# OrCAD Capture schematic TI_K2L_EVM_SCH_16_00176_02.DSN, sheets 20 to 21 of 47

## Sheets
20 PAGE20 : K2L_SOC-DDR3-2: size C; title: DDR3(3)
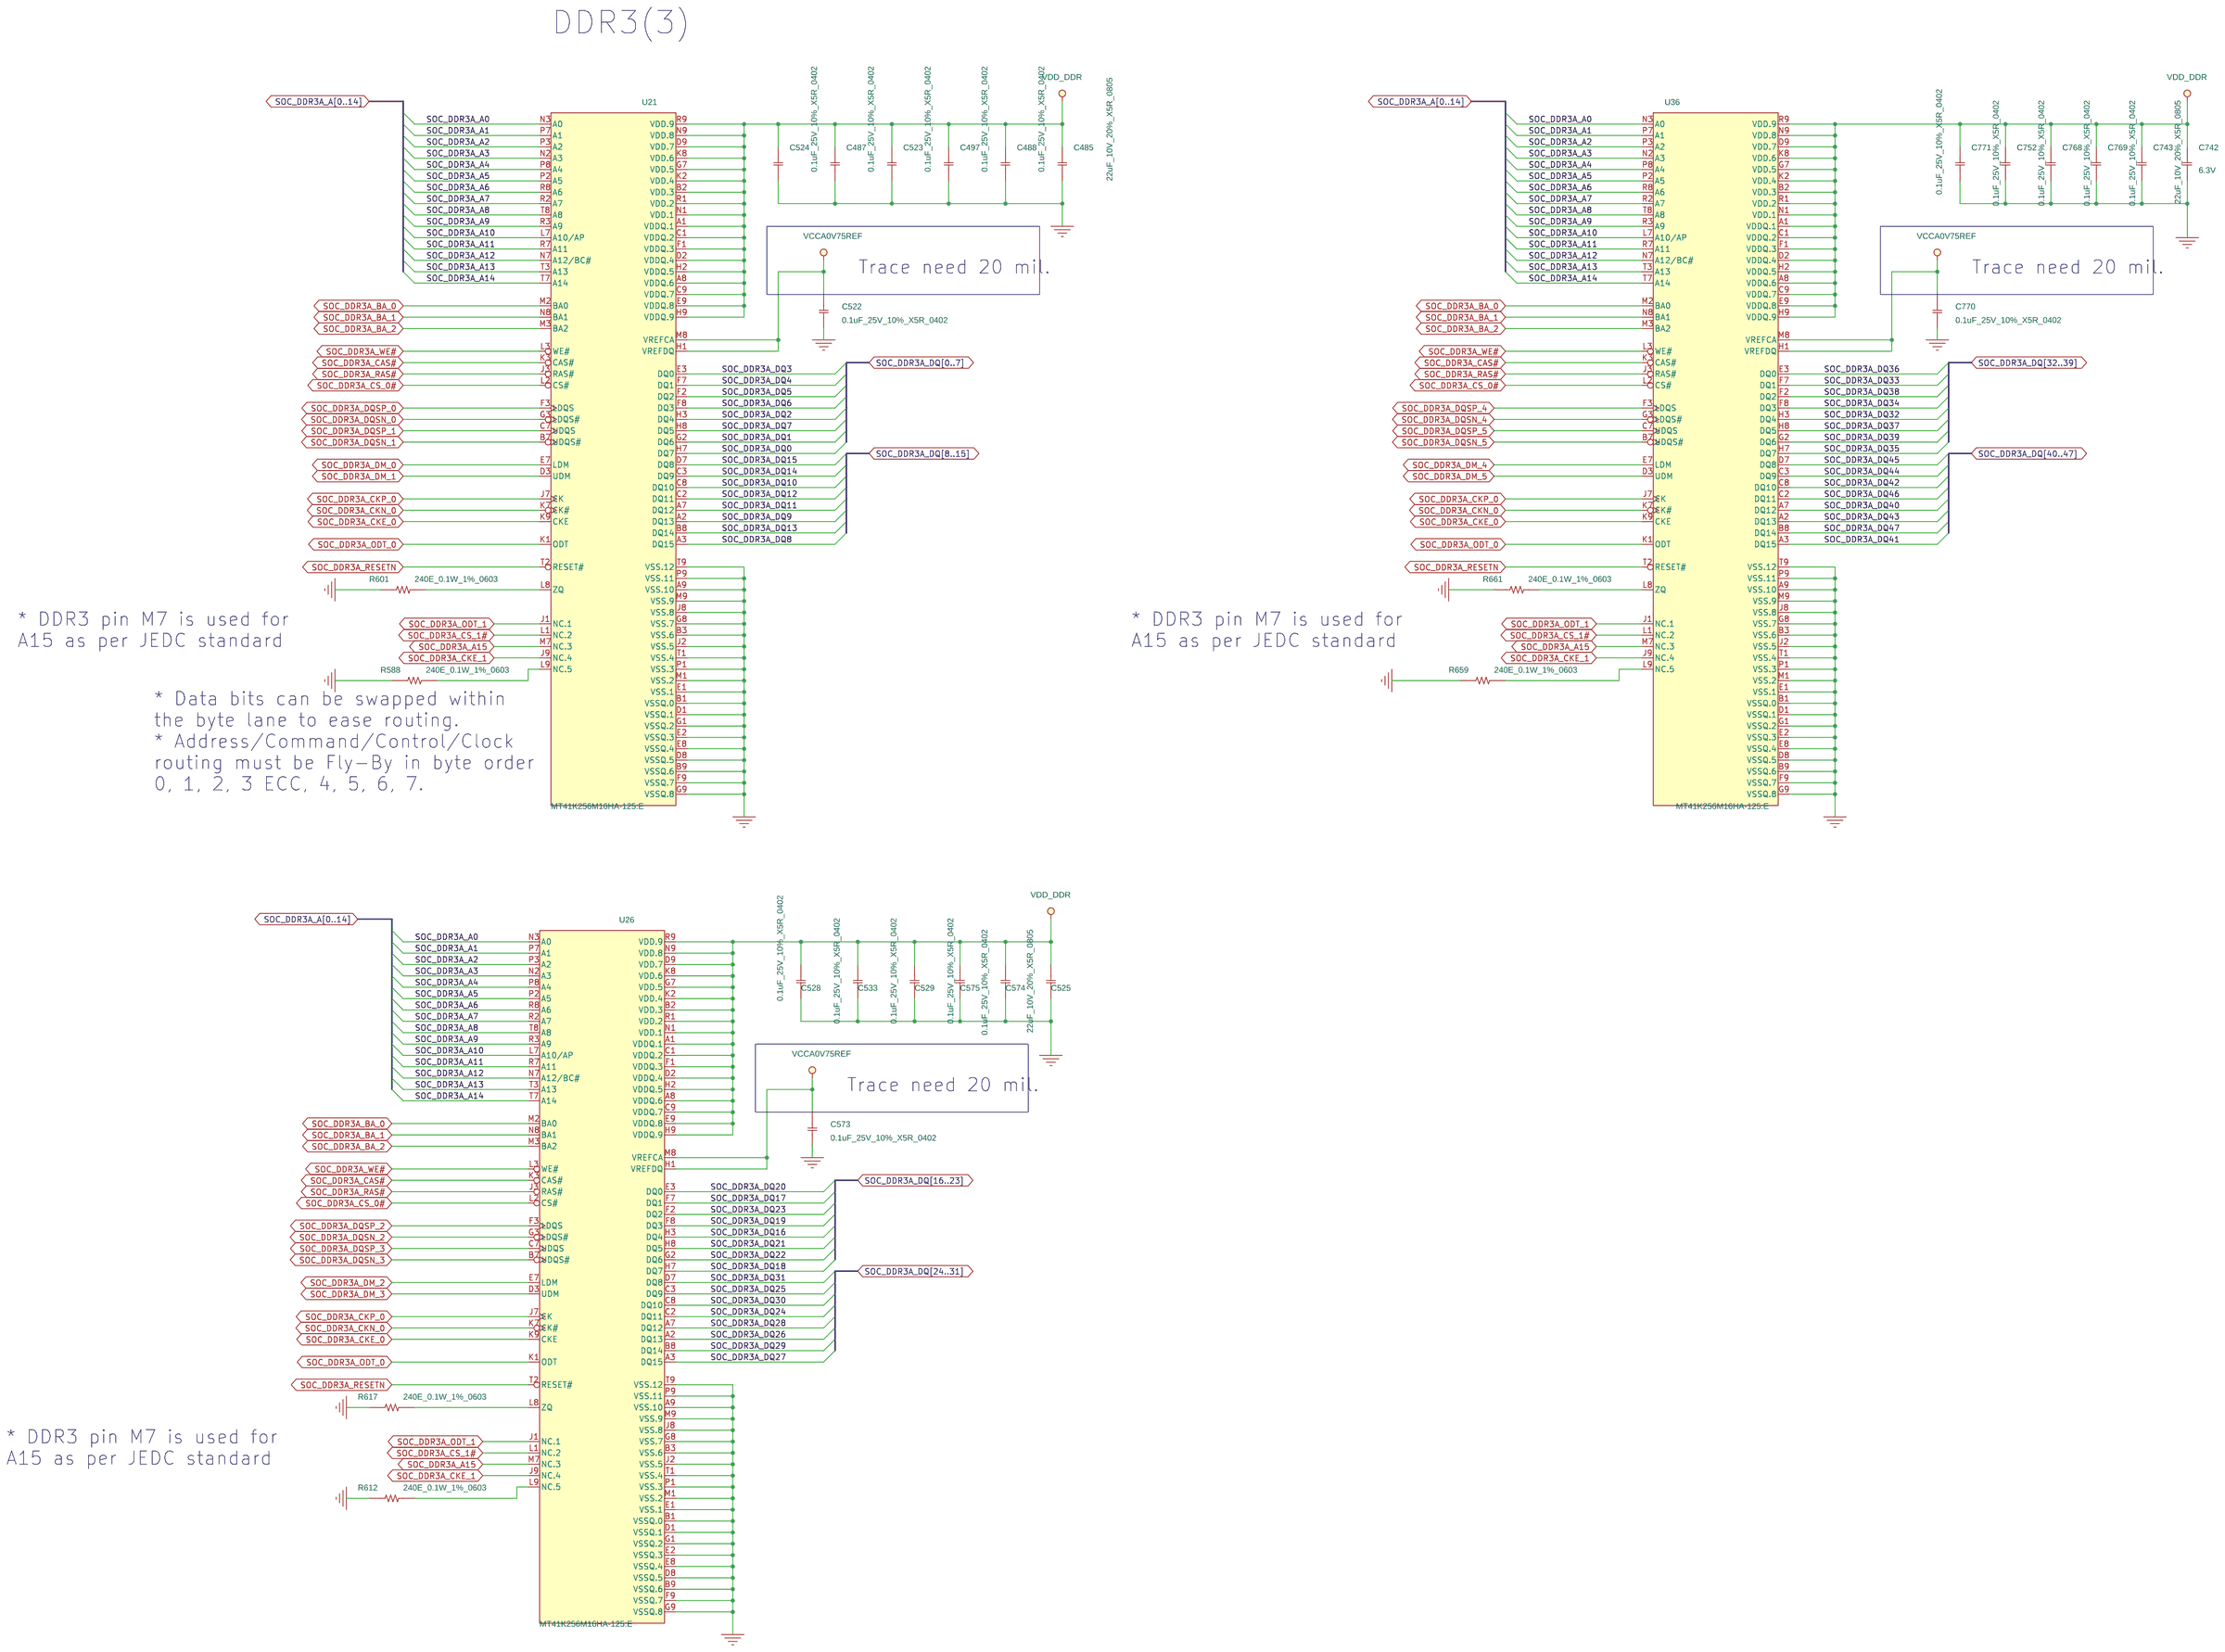
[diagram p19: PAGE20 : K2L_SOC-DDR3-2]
21 PAGE28 : K2L_BUFFER_EMIF: size C; title: EMIF Addr/Cntl Buffer, Ext EMIF_OE, EMIF Data Transceiver
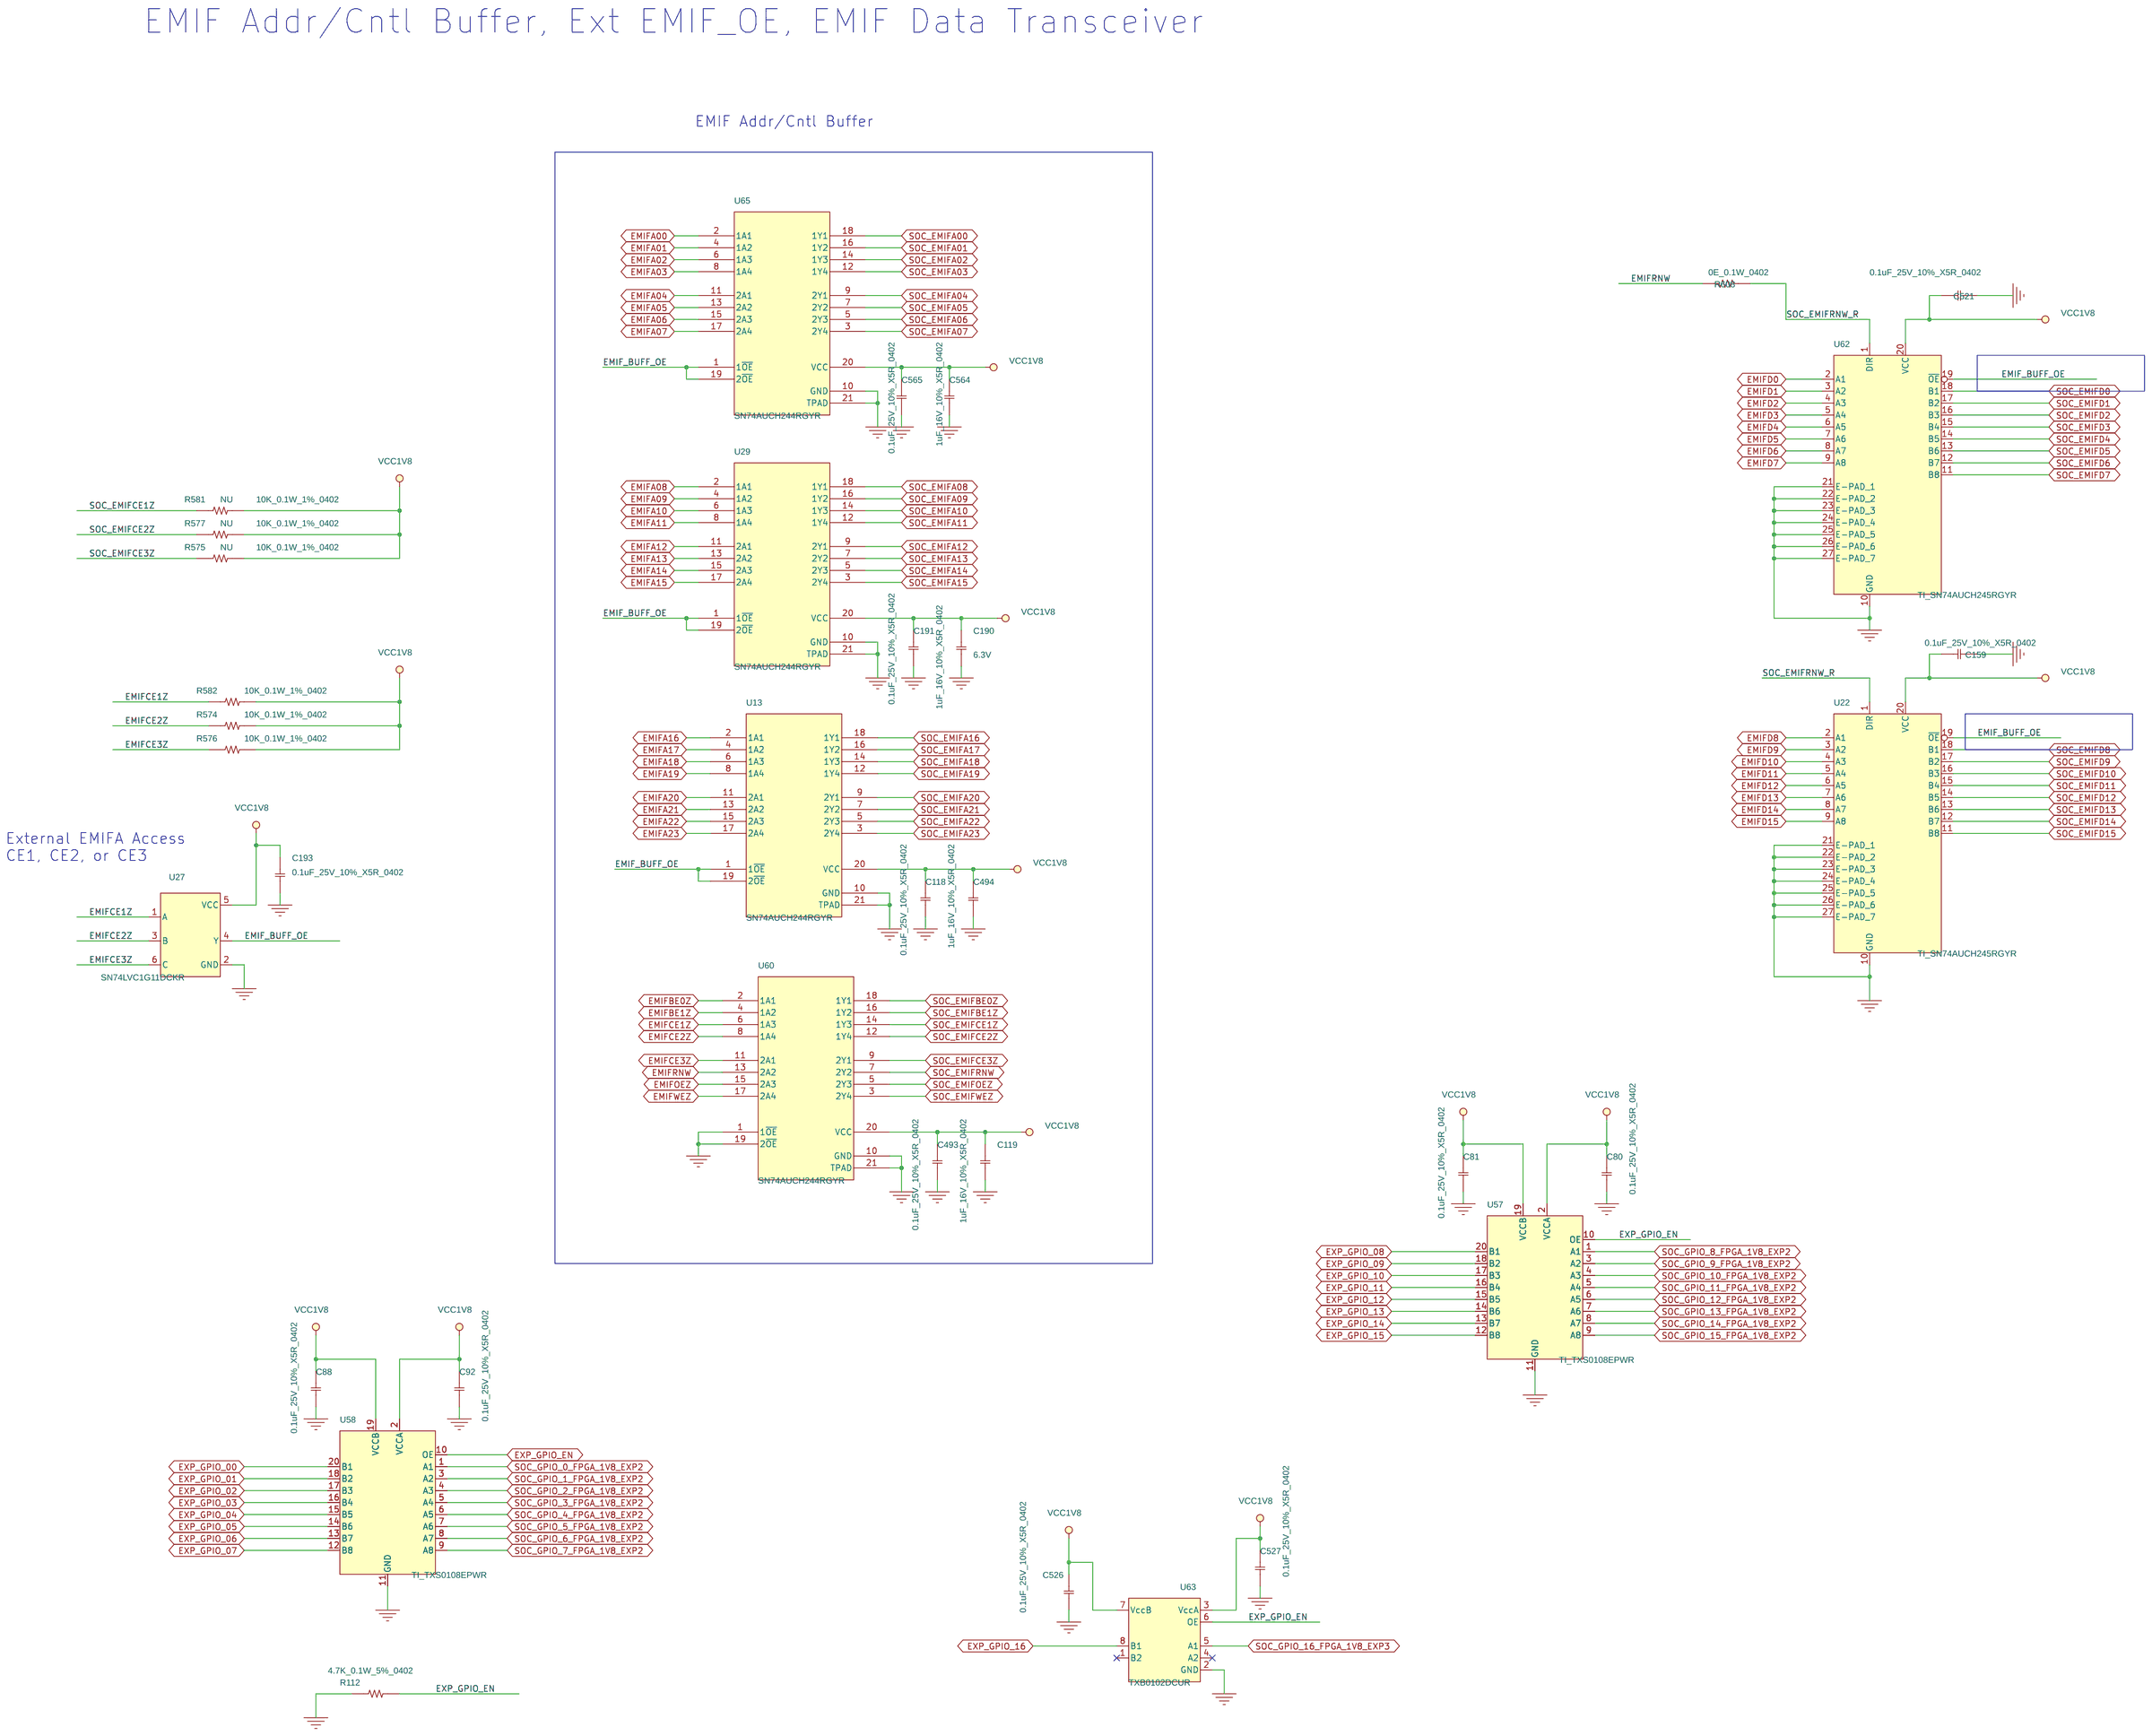
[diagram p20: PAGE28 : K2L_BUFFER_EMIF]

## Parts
sheet PAGE20 : K2L_SOC-DDR3-2
C485  22uF_10V_20%_X5R_0805  [C0805]
C487  0.1uF_25V_10%_X5R_0402  [C0402]
C488  0.1uF_25V_10%_X5R_0402  [C0402]
C497  0.1uF_25V_10%_X5R_0402  [C0402]
C522  0.1uF_25V_10%_X5R_0402  [C0402]
C523  0.1uF_25V_10%_X5R_0402  [C0402]
C524  0.1uF_25V_10%_X5R_0402  [C0402]
C525  22uF_10V_20%_X5R_0805  [C0805]
C528  0.1uF_25V_10%_X5R_0402  [C0402]
C529  0.1uF_25V_10%_X5R_0402  [C0402]
C533  0.1uF_25V_10%_X5R_0402  [C0402]
C573  0.1uF_25V_10%_X5R_0402  [C0402]
C574  0.1uF_25V_10%_X5R_0402  [C0402]
C575  0.1uF_25V_10%_X5R_0402  [C0402]
C742  22uF_10V_20%_X5R_0805  [C0805]
C743  0.1uF_25V_10%_X5R_0402  [C0402]
C752  0.1uF_25V_10%_X5R_0402  [C0402]
C768  0.1uF_25V_10%_X5R_0402  [C0402]
C769  0.1uF_25V_10%_X5R_0402  [C0402]
C770  0.1uF_25V_10%_X5R_0402  [C0402]
C771  0.1uF_25V_10%_X5R_0402  [C0402]
R588  240E_0.1W_1%_0603  [R0603]
R601  240E_0.1W_1%_0603  [R0603]
R612  240E_0.1W_1%_0603  [R0603]
R617  240E_0.1W_1%_0603  [R0603]
R659  240E_0.1W_1%_0603  [R0603]
R661  240E_0.1W_1%_0603  [R0603]
U21  MT41K256M16HA-125:E  [FBGA80P_9X14_96_EINF]
U26  MT41K256M16HA-125:E  [FBGA80P_9X14_96_EINF]
U36  MT41K256M16HA-125:E  [FBGA80P_9X14_96_EINF]
sheet PAGE28 : K2L_BUFFER_EMIF
C80  0.1uF_25V_10%_X5R_0402  [C0402]
C81  0.1uF_25V_10%_X5R_0402  [C0402]
C88  0.1uF_25V_10%_X5R_0402  [C0402]
C92  0.1uF_25V_10%_X5R_0402  [C0402]
C118  0.1uF_25V_10%_X5R_0402  [C0402]
C119  1uF_16V_10%_X5R_0402  [C0402]
C159  0.1uF_25V_10%_X5R_0402  [C0402]
C190  1uF_16V_10%_X5R_0402  [C0402]
C191  0.1uF_25V_10%_X5R_0402  [C0402]
C193  0.1uF_25V_10%_X5R_0402  [C0402]
C493  0.1uF_25V_10%_X5R_0402  [C0402]
C494  1uF_16V_10%_X5R_0402  [C0402]
C521  0.1uF_25V_10%_X5R_0402  [C0402]
C526  0.1uF_25V_10%_X5R_0402  [C0402]
C527  0.1uF_25V_10%_X5R_0402  [C0402]
C564  1uF_16V_10%_X5R_0402  [C0402]
C565  0.1uF_25V_10%_X5R_0402  [C0402]
R112  4.7K_0.1W_5%_0402  [R0402]
R574  10K_0.1W_1%_0402  [R0402]
R575  10K_0.1W_1%_0402  [R0402]
R576  10K_0.1W_1%_0402  [R0402]
R577  10K_0.1W_1%_0402  [R0402]
R581  10K_0.1W_1%_0402  [R0402]
R582  10K_0.1W_1%_0402  [R0402]
R608  0E_0.1W_0402  [R0402]
U13  SN74AUCH244RGYR  [VQFN50P450X350X100-21N_EINF]
U22  TI_SN74AUCH245RGYR  [QFN_20P_20_177x138_TP]
U27  SN74LVC1G11DCKR  [SC70_6p]
U29  SN74AUCH244RGYR  [VQFN50P450X350X100-21N_EINF]
U57  TI_TXS0108EPWR  [SOIC_20P_26_256x252]
U58  TI_TXS0108EPWR  [SOIC_20P_26_256x252]
U60  SN74AUCH244RGYR  [VQFN50P450X350X100-21N_EINF]
U62  TI_SN74AUCH245RGYR  [QFN_20P_20_177x138_TP]
U63  TXB0102DCUR  [VSSOP50P310_8]
U65  SN74AUCH244RGYR  [VQFN50P450X350X100-21N_EINF]

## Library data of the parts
C485 = 11_C_0: CAP CER 22UF 10V 20% X5R 0805; Distributor_name: DIGIKEY; Distributor_part_number: 587-1958-1-ND; EIC Part#: 03_00263_01; Manufacture: Taiyo Yuden; Manufacture Part Number: LMK212BJ226MG-T; Manufacture(English): Taiyo Yuden; Manufacture_Part_Number: LMK212BJ226MG-T; Manufacturer: Taiyo Yuden; Manufacturer_Part_No: LMK212BJ226MG-T; Mfg: Taiyo Yuden; Mfg Part#: 03_00263_01; Mfr_name: Taiyo Yuden; Mfr_part_number: LMK212BJ226MG-T; Package: 0805; Part_Number: 1100000254; Price @ 1: 0.53000; Price @ 10K: 0.12000; Price @ 1K: 0.16875; ProcessType: SMT; Tolerance: 20%; Vendor: DIGIKEY; Vendor Part#: 587-1958-1-ND; Vendor_Part_No: 587-1958-1-ND; eI Part#: 03_00263_01
C118 C159 C191 C487 C488 C493 C497 C521-C524 C528 C529 C533 C565 C573-C575 C743 C752 C768-C771 = 11_C_0: CAP CER 0.1UF 25V 10% X5R 0402; Avalue_Part_Number: E1123510400H; Distributor_name: DIGIKEY; Distributor_part_number: 445-4964-1-ND; EIC Part#: 03_00470_02; MOUNTED: <MOUNTED>; Manufacture: TDK Corporation; Manufacture Part Number: C1005X5R1E104K050BC; Manufacture(English): TDK Corporation; Manufacture_Part_Number: GRM155R71C104KA88D; Manufacturer: TDK Corporation; Manufacturer_Part_No: C1005X5R1E104K050BC; Mfg: Murata Electronics North America; Mfg Part#: 03_00470_02; Mfr_name: TDK Corporation; Mfr_part_number: C1005X5R1E104K050BC; Package: 0402; Price @ 1: 0.10000; Price @ 1K: 0.00420; ProcessType: SMT; Tolerance: 10%; Vendor: DIGIKEY; Vendor Part#: 445-4964-1-ND; Vendor_Part_No: 445-4964-1-ND; eI Part#: 03_00470_02
C525 C742 = 11_C_0: CAP CER 22UF 10V 20% X5R 0805; Characteristic: 6.3V; Distributor_name: DIGIKEY; Distributor_part_number: 587-1958-1-ND; EIC Part#: 03_00263_01; Manufacture: Taiyo Yuden; Manufacture Part Number: LMK212BJ226MG-T; Manufacture(English): Taiyo Yuden; Manufacture_Part_Number: LMK212BJ226MG-T; Manufacturer: Taiyo Yuden; Manufacturer_Part_No: LMK212BJ226MG-T; Mfg: Taiyo Yuden; Mfg Part#: 03_00263_01; Mfr_name: Taiyo Yuden; Mfr_part_number: LMK212BJ226MG-T; Package: 0805; Part_Number: 1100000254; Price @ 1: 0.53000; Price @ 10K: 0.12000; Price @ 1K: 0.16875; ProcessType: SMT; Tolerance: 20%; Vendor: DIGIKEY; Vendor Part#: 587-1958-1-ND; Vendor_Part_No: 587-1958-1-ND; eI Part#: 03_00263_01
R588 = 10_R_0: RES 240 OHM 1/10W 1% 0603 SMD; Characteristic: 1%; Distributor_name: DIGIKEY; Distributor_part_number: P240HCT-ND; EIC Part#: 02_00734_01; Manufacture: Panasonic - ECG; Manufacture Part Number: ERJ-3EKF2400V; Manufacture(English): Panasonic - ECG; Manufacture_Part_Number: ERJ-3EKF2400V; Manufacturer: Panasonic - ECG; Manufacturer_Part_No: ERJ-3EKF2400V; Mfg: Panasonic Electronic Components; Mfg Part#: 02_00734_01; Mfr_name: Panasonic - ECG; Mfr_part_number: ERJ-3EKF2400V; Package: 0603; Part_Number: 105A524003; Price @ 1: 0.10000; Price @ 10K: 0.00247; Price @ 1K: 0.00416; ProcessType: SMT; Tolerance: 1%; Vendor: DIGIKEY; Vendor_Part_No: P240HCT-ND; eI Part#: 02_00032_01
R601 = 10_R_0: RES 240 OHM 1/10W 1% 0603 SMD; Characteristic: 1%; Distributor_name: DIGIKEY; Distributor_part_number: P240HCT-ND; EIC Part#: 02_00734_01; Manufacture: Panasonic - ECG; Manufacture Part Number: ERJ-3EKF2400V; Manufacture(English): Panasonic - ECG; Manufacture_Part_Number: ERJ-3EKF2400V; Manufacturer: Panasonic - ECG; Manufacturer_Part_No: ERJ-3EKF2400V; Mfg: Panasonic Electronic Components; Mfg Part#: 02_00734_01; Mfr_name: Panasonic - ECG; Mfr_part_number: ERJ-3EKF2400V; Package: 0603; Part_Number: 105A524003; Price @ 1: 0.10000; Price @ 10K: 0.00247; Price @ 1K: 0.00416; ProcessType: SMT; Tolerance: 1%; Vendor: DIGIKEY; Vendor_Part_No: P240HCT-ND; eI Part#: 02_00195_04
R612 R617 R659 = 10_R_0: RES 240 OHM 1/10W 1% 0603 SMD; Characteristic: 1%; Distributor_name: DIGIKEY; Distributor_part_number: P240HCT-ND; EIC Part#: 02_00734_01; Manufacture: Panasonic - ECG; Manufacture Part Number: ERJ-3EKF2400V; Manufacture(English): Panasonic - ECG; Manufacture_Part_Number: ERJ-3EKF2400V; Manufacturer: Panasonic - ECG; Manufacturer_Part_No: ERJ-3EKF2400V; Mfg: Panasonic Electronic Components; Mfg Part#: 02_00734_01; Mfr_name: Panasonic - ECG; Mfr_part_number: ERJ-3EKF2400V; Package: 0603; Part_Number: 105A524003; Price @ 1: 0.10000; Price @ 10K: 0.00247; Price @ 1K: 0.00416; ProcessType: SMT; Tolerance: 1%; Vendor: DIGIKEY; Vendor_Part_No: P240HCT-ND; eI Part#: 02_00027_01
R661 = 10_R_0: RES 240 OHM 1/10W 1% 0603 SMD; Characteristic: 1%; Distributor_name: DIGIKEY; Distributor_part_number: P240HCT-ND; EIC Part#: 02_00734_01; Manufacture: Panasonic - ECG; Manufacture Part Number: ERJ-3EKF2400V; Manufacture(English): Panasonic - ECG; Manufacture_Part_Number: ERJ-3EKF2400V; Manufacturer: Panasonic - ECG; Manufacturer_Part_No: ERJ-3EKF2400V; Mfg: Panasonic Electronic Components; Mfg Part#: 02_00734_01; Mfr_name: Panasonic - ECG; Mfr_part_number: ERJ-3EKF2400V; Package: 0603; Part_Number: 105A524003; Price @ 1: 0.10000; Price @ 10K: 0.00247; Price @ 1K: 0.00416; ProcessType: SMT; Tolerance: 1%; Vendor: DIGIKEY; Vendor_Part_No: P240HCT-ND; eI Part#: 02_00734_01
U21 U26 U36 = MT41K256M16HA_0: IC DDR3 SDRAM 4GBIT 96FBGA; Distributor_name: DIGIKEY; Distributor_part_number: MT41K256M16HA-125:E-ND; EIC Part#: 01_01147_01; Manufacture: Micron; Manufacture(English): Micron; Manufacturer: Micron; Mfg Part#: 01_01147_01; Mfr_name: Micron; Price @ 1K: 8.65215; Vendor: DIGIKEY; Vendor part#: MT41K256M16HA125:E; Vendor_Part_No: MT41K256M16HA-125:E-ND; eI Part#: 01_01149_01; itemp Part#: MT41K256M16HA125:E
C80 C81 C88 C92 C193 C526 C527 = 11_C_12: CAP CER 0.1UF 25V 10% X5R 0402; Alt Mfg: Taiyo Yuden; Distributor_name: DIGIKEY; Distributor_part_number: 445-4964-1-ND; EIC Part#: 03_00470_02; Manufacture: TDK Corporation; Manufacture Part Number: C1005X5R1E104K050BC; Manufacture(English): TDK Corporation; Manufacture_Part_Number: GRM155R61E104KA87D; Manufacturer: TDK Corporation; Manufacturer_Part_No: C1005X5R1E104K050BC; Mfg: Murata Electronics North America; Mfg Part#: 03_00470_02; Mfr_name: TDK Corporation; Mfr_part_number: C1005X5R1E104K050BC; Oper. Temp. Range: -55°C ~ 85°C; Package: 0402; Price @ 1: 0.10000; Price @ 1K: 0.00960; ProcessType: SMT; RoHS: Yes; Tolerance: 10%; Vendor: DIGIKEY; Vendor Part#: 445-4964-1-ND; Vendor_Part_No: 445-4964-1-ND; eI Part#: 03_00470_02
C119 C190 C494 C564 = 11_C_0: CAP CER 1UF 16V 10% X5R 0402; Characteristic: 6.3V; Distributor_name: DIGIKEY; Distributor_part_number: 445-4978-1-ND; EIC Part#: 03_00355_04; Manufacture: TDK Corporation; Manufacture Part Number: C1005X5R1C105K050BC; Manufacture(English): TDK Corporation; Manufacture_Part_Number: C1005X5R1C105K050BC; Manufacturer: TDK Corporation; Manufacturer_Part_No: C1005X5R1C105K050BC; Mfg: TDK Corporation; Mfg Part#: C1005X5R1C105K050BC; Mfr_name: TDK Corporation; Mfr_part_number: C1005X5R1C105K050BC; Package: 0402; Part_Number: 1100000870; Price @ 1: 0.10000; Price @ 10K: 0.01155; Price @ 1K: 0.01650; ProcessType: SMT; Tolerance: 10%; Vendor: DIGIKEY; Vendor_Part_No: 445-4978-1-ND; eI Part#: 03_00355_04
R112 = 10_R_0: RES 4.7K OHM 1/10W 5% 0402 SMD; Alt Mfg: Yageo; Alt Mfg Part#: RC0402JR-074K7L; Distributor_name: DIGIKEY; Distributor_part_number: P4.7KJCT-ND; EIC Part#: 02_00023_01; Manufacture: Panasonic - ECG; Manufacture Part Number: ERJ-2GEJ472X; Manufacture(English): Panasonic - ECG; Manufacture_Part_Number: ERJ-2GEJ472X; Manufacturer: Panasonic - ECG; Manufacturer_Part_No: ERJ-2GEJ472X; Mfg Part#: 02_00023_01; Mfr_name: Panasonic - ECG; Mfr_part_number: ERJ-2GEJ472X; Oper. Temp. Range: -55C to 125C; Package: 0402; ProcessType: SMT; Remark: Alt part is 1/16W; RoHS: Yes; Tolerance: 1%; Vendor: DIGIKEY; Vendor Part#: P4.7KJCT-ND; Vendor_Part_No: P4.7KJCT-ND; eI Part#: 02_00023_01
R574 R576 R582 = 10_R_0: RES 10K OHM 1/10W 1% 0402 SMD; Characteristic: 1%; Distributor_name: DIGIKEY; Distributor_part_number: P10.0KLCT-ND; EIC Part#: 02_00027_01; Manufacture: Panasonic - ECG; Manufacture Part Number: ERJ-2RKF1002X; Manufacture(English): Panasonic - ECG; Manufacture_Part_Number: ERJ-2RKF1002X; Manufacturer: Panasonic - ECG; Manufacturer_Part_No: ERJ-2RKF1002X; Mfg: PANASONIC ELECTRONIC COMPONENTS (VA); Mfg Part#: 02_00027_01; Mfr_name: Panasonic - ECG; Mfr_part_number: ERJ-2RKF1002X; Package: 0402; Part_Number: 105A50103A; Price @ 1: 0.10000; Price @ 10K: 0.00347; Price @ 1K: 0.00672; ProcessType: SMT; Tolerance: 1%; Vendor: DIGIKEY; Vendor_Part_No: P10.0KLCT-ND; eI Part#: 02_00027_01
R575 R577 R581 = 10_R_0: RES 10K OHM 1/10W 1% 0402 SMD; Characteristic: 1%; Distributor_name: DIGIKEY; Distributor_part_number: P10.0KLCT-ND; EIC Part#: 02_00027_01; Manufacture: Panasonic - ECG; Manufacture Part Number: ERJ-2RKF1002X; Manufacture(English): Panasonic - ECG; Manufacture_Part_Number: ERJ-2RKF1002X; Manufacturer: Panasonic - ECG; Manufacturer_Part_No: ERJ-2RKF1002X; Mfg: PANASONIC ELECTRONIC COMPONENTS (VA); Mfg Part#: 02_00027_01; Mfr_name: Panasonic - ECG; Mfr_part_number: ERJ-2RKF1002X; Mounting: NU; Mounting Status: NU; Mounting_Status: NU; Package: 0402; Part_Number: 105A50103A; Price @ 1: 0.10000; Price @ 10K: 0.00347; Price @ 1K: 0.00672; ProcessType: SMT; Tolerance: 1%; Vendor: DIGIKEY; Vendor_Part_No: P10.0KLCT-ND; eI Part#: 02_00027_01
R608 = 10_R_0: RES 0.0 OHM 1/10W JUMP 0402 SMD; Characteristic: 5%; Distributor_name: DIGIKEY; Distributor_part_number: P0.0JCT-ND; EIC Part#: 02_00019_01; MOUNTED: <MOUNTED>; Manufacture: Panasonic - ECG; Manufacture Part Number: ERJ-2GE0R00X; Manufacture(English): Panasonic - ECG; Manufacture_Part_Number: ERJ-2GE0R00X; Manufacturer: Panasonic - ECG; Manufacturer_Part_No: ERJ-2GE0R00X; Mfg: Panasonic Electronic Components; Mfg Part#: 02_00019_01; Mfr_name: Panasonic - ECG; Mfr_part_number: ERJ-2GE0R00X; Package: 0402; Part_Number: 105A700004; Price @ 1: 0.05000; Price @ 10K: 0.00248; Price @ 1K: 0.00480; ProcessType: SMT; Tolerance: 5%; Vendor: DIGIKEY; Vendor_Part_No: P0.0JCT-ND; eI Part#: 02_00019_01
U13 U60 = SN74AUCH244RGYR: IC BUFF/DVR TRI-ST DUAL 20QFN; Distributor_name: DIGIKEY; Distributor_part_number: 296-19068-1-ND; EIC Part#: 01_01158_01; Manufacture: TI; Manufacture(English): TI; Manufacturer: TI; Mfg: TI; Mfg Part#: 01_01158_01; Mfr_name: TI; Package: 20QFN; Price @ 1: 1.59000; Price @ 10K: 0.61600; Price @ 1K: 0.68200; Vendor: DIGIKEY; Vendor_Part_No: 296-19068-1-ND; eI Part#: 01_01158_01
U22 = 141_TI_SN74AUCH245RGYR_1: IC BUS TRANSCVR 8BIT 20QFN; Distributor_name: DIGIKEY; Distributor_part_number: 296-15444-1-ND; EIC Part#: 01_01125_01; Manufacture: TI; Manufacture Part Number: SN74AUCH245RGYR; Manufacture(English): TI; Manufacture_Part_Number: SN74AUCH245RGYR; Manufacturer: TI; Manufacturer_Part_No: SN74AUCH245RGYR; Mfg: TI; Mfg Part#: 01_01125_01; Mfr_name: TI; Mfr_part_number: SN74AUCH245RGYR; Package: VQFN20; Part_Number: 1410023911-01; Price @ 1: 1.59000; Price @ 10K: 0.61600; Price @ 1K: 0.68200; Tolerance: NA; Vendor: DIGIKEY; Vendor_Part_No: 296-15444-1-ND; eI Part#: 01_00391_01
U27 = SN74LVC1G11DCKR: IC SNGL 3IN POS AND GATE SC70-6; Distributor_name: DIGIKEY; Distributor_part_number: 296-18066-1-ND; EIC Part#: 01_00049_01; Manufacture: TI; Manufacture(English): TI; Manufacturer: TI; Mfg: TI; Mfg Part#: 01_00049_01; Mfr_name: TI; Price @ 1: 0.40000; Price @ 10K: 0.09900; Price @ 1K: 0.11100; RoHS: Yes; Vendor: DIGIKEY; Vendor Part#: 296-18066-1-ND; Vendor_Part_No: 296-18066-1-ND; eI Part#: 01_00049_01
U29 = SN74AUCH244RGYR: IC BUFF/DVR TRI-ST DUAL 20QFN; Distributor_name: DIGIKEY; Distributor_part_number: 296-19068-1-ND; EIC Part#: 01_01158_01; Manufacture: TI; Manufacture(English): TI; Manufacturer: TI; Mfg: TI; Mfg Part#: 01_01158_01; Mfr_name: TI; Package: 20QFN; Price @ 1: 1.59000; Price @ 10K: 0.61600; Price @ 1K: 0.68200; Vendor: DIGIKEY; Vendor_Part_No: 296-19068-1-ND; eI Part#: 01_01129_01
U57 = 141_TI_TXS0108EPWR_0: IC 8BIT NON-INV TRANSLTR 20TSSOP; Distributor_name: DIGIKEY; Distributor_part_number: 296-23011-1-ND; EIC Part#: 01_00472_01; Manufacture: TI; Manufacture Part Number: TXS0108EPWR; Manufacture(English): TI; Manufacture_Part_Number: TXS0108EPWR; Manufacturer: TI; Manufacturer_Part_No: TXS0108EPWR; Mfg: TI; Mfg Part#: 01_00472_01; Mfr_name: TI; Mfr_part_number: TXS0108EPWR; Oper. Temp. Range: -40°C ~ 85°C; Package: TSSOP20; Part_Number: 1410020326; Price @ 1: 2.30000; Price @ 10K: 0.90000; Price @ 1K: 0.91800; ProcessType: SMT; RoHS: Yes; Vendor: DIGIKEY; Vendor Part#: 296-23011-1-ND; Vendor_Part_No: 296-23011-1-ND; eI Part#: 01_00049_01
U58 = 141_TI_TXS0108EPWR_0: IC 8BIT NON-INV TRANSLTR 20TSSOP; Distributor_name: DIGIKEY; Distributor_part_number: 296-23011-1-ND; EIC Part#: 01_00472_01; Manufacture: TI; Manufacture Part Number: TXS0108EPWR; Manufacture(English): TI; Manufacture_Part_Number: TXS0108EPWR; Manufacturer: TI; Manufacturer_Part_No: TXS0108EPWR; Mfg: TI; Mfg Part#: 01_00472_01; Mfr_name: TI; Mfr_part_number: TXS0108EPWR; Oper. Temp. Range: -40°C ~ 85°C; Package: TSSOP20; Part_Number: 1410020326; Price @ 1: 2.30000; Price @ 10K: 0.90000; Price @ 1K: 0.91800; ProcessType: SMT; RoHS: Yes; Vendor: DIGIKEY; Vendor Part#: 296-23011-1-ND; Vendor_Part_No: 296-23011-1-ND; eI Part#: 01_00472_01
U62 = 141_TI_SN74AUCH245RGYR_0: IC BUS TRANSCVR 8BIT 20QFN; Distributor_name: DIGIKEY; Distributor_part_number: 296-15444-1-ND; EIC Part#: 01_01125_01; Manufacture: TI; Manufacture Part Number: SN74AUCH245RGYR; Manufacture(English): TI; Manufacture_Part_Number: SN74AUCH245RGYR; Manufacturer: TI; Manufacturer_Part_No: SN74AUCH245RGYR; Mfg: TI; Mfg Part#: 01_01125_01; Mfr_name: TI; Mfr_part_number: SN74AUCH245RGYR; Package: VQFN20; Part_Number: 1410023911-01; Price @ 1: 1.59000; Price @ 10K: 0.61600; Price @ 1K: 0.68200; Tolerance: NA; Vendor: DIGIKEY; Vendor_Part_No: 296-15444-1-ND; eI Part#: 01_01129_01
U63 = TXS0102_0: IC VOLT-LEVEL TRANSLATOR US8; Distributor_name: DIGIKEY; Distributor_part_number: TBD; EIC Part#: TBD; Manufacture: TI; Manufacture(English): TI; Manufacturer: TI; Mfg: TI; Mfg Part#: TBD; Mfr_name: TI; Package: 8-VFSOP; Price @ 1: 1.07000; Price @ 10K: 0.37125; Price @ 1K: 0.37868; RoHS: Yes; Vendor: DIGIKEY; Vendor Part#: TBD; Vendor_Part_No: TBD; eI Part#: TBD
U65 = SN74AUCH244RGYR: IC BUFF/DVR TRI-ST DUAL 20QFN; Distributor_name: DIGIKEY; Distributor_part_number: 296-19068-1-ND; EIC Part#: 01_01158_01; Manufacture: TI; Manufacture(English): TI; Manufacturer: TI; Mfg: TI; Mfg Part#: 01_01158_01; Mfr_name: TI; Package: 20QFN; Price @ 1: 1.59000; Price @ 10K: 0.61600; Price @ 1K: 0.68200; Vendor: DIGIKEY; Vendor_Part_No: 296-19068-1-ND; eI Part#: 01_00039_01

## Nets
GND: C80.2 C81.2 C88.2 C92.2 C118.1 C119.2 C159.2 C190.2 C191.1 C193.2 C485.2 C487.2 C488.2 C493.1 C494.2 C497.2 C521.2 C522.2 C523.2 C524.2 C525.2 C526.2 C527.2 C528.2 C529.2 C533.2 C564.2 C565.1 C573.2 C574.2 C575.2 C742.2 C743.2 C752.2 C768.2 C769.2 C770.2 C771.2 R112.1 R588.1 R601.1 R612.1 R617.1 R659.1 R661.1 U13.10(GND) U13.21(TPAD) U21.A9(VSS.10) U21.B1(VSSQ.0) U21.B3(VSS.6) U21.B9(VSSQ.6) U21.D1(VSSQ.1) U21.D8(VSSQ.5) U21.E1(VSS.1) U21.E2(VSSQ.3) U21.E8(VSSQ.4) U21.F9(VSSQ.7) U21.G1(VSSQ.2) U21.G8(VSS.7) U21.G9(VSSQ.8) U21.J2(VSS.5) U21.J8(VSS.8) U21.M1(VSS.2) U21.M9(VSS.9) U21.P1(VSS.3) U21.P9(VSS.11) U21.T1(VSS.4) U21.T9(VSS.12) U22.10(GND) U22.21(E-PAD_1) U22.22(E-PAD_2) U22.23(E-PAD_3) U22.24(E-PAD_4) U22.25(E-PAD_5) U22.26(E-PAD_6) U22.27(E-PAD_7) U26.A9(VSS.10) U26.B1(VSSQ.0) U26.B3(VSS.6) U26.B9(VSSQ.6) U26.D1(VSSQ.1) U26.D8(VSSQ.5) U26.E1(VSS.1) U26.E2(VSSQ.3) U26.E8(VSSQ.4) U26.F9(VSSQ.7) U26.G1(VSSQ.2) U26.G8(VSS.7) U26.G9(VSSQ.8) U26.J2(VSS.5) U26.J8(VSS.8) U26.M1(VSS.2) U26.M9(VSS.9) U26.P1(VSS.3) U26.P9(VSS.11) U26.T1(VSS.4) U26.T9(VSS.12) U27.2(GND) U29.10(GND) U29.21(TPAD) U36.A9(VSS.10) U36.B1(VSSQ.0) U36.B3(VSS.6) U36.B9(VSSQ.6) U36.D1(VSSQ.1) U36.D8(VSSQ.5) U36.E1(VSS.1) U36.E2(VSSQ.3) U36.E8(VSSQ.4) U36.F9(VSSQ.7) U36.G1(VSSQ.2) U36.G8(VSS.7) U36.G9(VSSQ.8) U36.J2(VSS.5) U36.J8(VSS.8) U36.M1(VSS.2) U36.M9(VSS.9) U36.P1(VSS.3) U36.P9(VSS.11) U36.T1(VSS.4) U36.T9(VSS.12) U57.11(GND) U58.11(GND) U60.1(1~{OE}) U60.10(GND) U60.19(2~{OE}) U60.21(TPAD) U62.10(GND) U62.21(E-PAD_1) U62.22(E-PAD_2) U62.23(E-PAD_3) U62.24(E-PAD_4) U62.25(E-PAD_5) U62.26(E-PAD_6) U62.27(E-PAD_7) U63.2(GND) U65.10(GND) U65.21(TPAD) ; also on sheet 1 2 3 4 5 6 8 10 11 12 13 14 15 16 17 18 19 22 24 25 26 27 28 29 33 34 35 36 37 40 41 42 43 45 46 47
VCC1V8: C80.1 C81.1 C88.1 C92.1 C118.2 C119.1 C159.1 C190.1 C191.2 C193.1 C493.2 C494.1 C521.1 C526.1 C527.1 C564.1 C565.2 R574.1 R575.1 R576.1 R577.1 R581.1 R582.1 U13.20(VCC) U22.20(VCC) U27.5(VCC) U29.20(VCC) U57.2(VCCA) U57.19(VCCB) U58.2(VCCA) U58.19(VCCB) U60.20(VCC) U62.20(VCC) U63.3(VccA) U63.7(VccB) U65.20(VCC) ; also on sheet 2 6 8 11 19 22 25 26 27 29 33 34 36 37 41
VCCA0V75REF: C522.1 C573.1 C770.1 U21.H1(VREFDQ) U21.M8(VREFCA) U26.H1(VREFDQ) U26.M8(VREFCA) U36.H1(VREFDQ) U36.M8(VREFCA) ; also on sheet 1 19
VDD_DDR: C485.1 C487.1 C488.1 C497.1 C523.1 C524.1 C525.1 C528.1 C529.1 C533.1 C574.1 C575.1 C742.1 C743.1 C752.1 C768.1 C769.1 C771.1 U21.A1(VDDQ.1) U21.A8(VDDQ.6) U21.B2(VDD.3) U21.C1(VDDQ.2) U21.C9(VDDQ.7) U21.D2(VDDQ.4) U21.D9(VDD.7) U21.E9(VDDQ.8) U21.F1(VDDQ.3) U21.G7(VDD.5) U21.H2(VDDQ.5) U21.H9(VDDQ.9) U21.K2(VDD.4) U21.K8(VDD.6) U21.N1(VDD.1) U21.N9(VDD.8) U21.R1(VDD.2) U21.R9(VDD.9) U26.A1(VDDQ.1) U26.A8(VDDQ.6) U26.B2(VDD.3) U26.C1(VDDQ.2) U26.C9(VDDQ.7) U26.D2(VDDQ.4) U26.D9(VDD.7) U26.E9(VDDQ.8) U26.F1(VDDQ.3) U26.G7(VDD.5) U26.H2(VDDQ.5) U26.H9(VDDQ.9) U26.K2(VDD.4) U26.K8(VDD.6) U26.N1(VDD.1) U26.N9(VDD.8) U26.R1(VDD.2) U26.R9(VDD.9) U36.A1(VDDQ.1) U36.A8(VDDQ.6) U36.B2(VDD.3) U36.C1(VDDQ.2) U36.C9(VDDQ.7) U36.D2(VDDQ.4) U36.D9(VDD.7) U36.E9(VDDQ.8) U36.F1(VDDQ.3) U36.G7(VDD.5) U36.H2(VDDQ.5) U36.H9(VDDQ.9) U36.K2(VDD.4) U36.K8(VDD.6) U36.N1(VDD.1) U36.N9(VDD.8) U36.R1(VDD.2) U36.R9(VDD.9) ; also on sheet 1 19 33 35 37
EMIF_BUFF_OE: U13.1(1~{OE}) U13.19(2~{OE}) U22.19(~{OE}) U27.4(Y) U29.1(1~{OE}) U29.19(2~{OE}) U62.19(~{OE}) U65.1(1~{OE}) U65.19(2~{OE})
EMIFA00: U65.2(1A1) ; also on sheet 41
EMIFA01: U65.4(1A2) ; also on sheet 41
EMIFA02: U65.6(1A3) ; also on sheet 41
EMIFA03: U65.8(1A4) ; also on sheet 41
EMIFA04: U65.11(2A1) ; also on sheet 41
EMIFA05: U65.13(2A2) ; also on sheet 41
EMIFA06: U65.15(2A3) ; also on sheet 41
EMIFA07: U65.17(2A4) ; also on sheet 41
EMIFA08: U29.2(1A1) ; also on sheet 41
EMIFA09: U29.4(1A2) ; also on sheet 41
EMIFA10: U29.6(1A3) ; also on sheet 41
EMIFA11: U29.8(1A4) ; also on sheet 41
EMIFA12: U29.11(2A1) ; also on sheet 41
EMIFA13: U29.13(2A2) ; also on sheet 41
EMIFA14: U29.15(2A3) ; also on sheet 41
EMIFA15: U29.17(2A4) ; also on sheet 41
EMIFA16: U13.2(1A1) ; also on sheet 41
EMIFA17: U13.4(1A2) ; also on sheet 41
EMIFA18: U13.6(1A3) ; also on sheet 41
EMIFA19: U13.8(1A4) ; also on sheet 41
EMIFA20: U13.11(2A1) ; also on sheet 41
EMIFA21: U13.13(2A2) ; also on sheet 41
EMIFA22: U13.15(2A3) ; also on sheet 41
EMIFA23: U13.17(2A4) ; also on sheet 41
EMIFBE0Z: U60.2(1A1) ; also on sheet 41
EMIFBE1Z: U60.4(1A2) ; also on sheet 41
EMIFCE1Z: R582.2 U27.1(A) U60.6(1A3) ; also on sheet 41
EMIFCE2Z: R574.2 U27.3(B) U60.8(1A4) ; also on sheet 41
EMIFCE3Z: R576.2 U27.6(C) U60.11(2A1) ; also on sheet 41
EMIFD0: U62.2(A1) ; also on sheet 41
EMIFD1: U62.3(A2) ; also on sheet 41
EMIFD2: U62.4(A3) ; also on sheet 41
EMIFD3: U62.5(A4) ; also on sheet 41
EMIFD4: U62.6(A5) ; also on sheet 41
EMIFD5: U62.7(A6) ; also on sheet 41
EMIFD6: U62.8(A7) ; also on sheet 41
EMIFD7: U62.9(A8) ; also on sheet 41
EMIFD8: U22.2(A1) ; also on sheet 41
EMIFD9: U22.3(A2) ; also on sheet 41
EMIFD10: U22.4(A3) ; also on sheet 41
EMIFD11: U22.5(A4) ; also on sheet 41
EMIFD12: U22.6(A5) ; also on sheet 41
EMIFD13: U22.7(A6) ; also on sheet 41
EMIFD14: U22.8(A7) ; also on sheet 41
EMIFD15: U22.9(A8) ; also on sheet 41
EMIFOEZ: U60.15(2A3) ; also on sheet 41
EMIFRNW: R608.2 U60.13(2A2) ; also on sheet 41
EMIFWEZ: U60.17(2A4) ; also on sheet 41
EXP_GPIO_00: U58.20(B1) ; also on sheet 26
EXP_GPIO_01: U58.18(B2) ; also on sheet 26
EXP_GPIO_02: U58.17(B3) ; also on sheet 26
EXP_GPIO_03: U58.16(B4) ; also on sheet 26
EXP_GPIO_04: U58.15(B5) ; also on sheet 26
EXP_GPIO_05: U58.14(B6) ; also on sheet 26
EXP_GPIO_06: U58.13(B7) ; also on sheet 26
EXP_GPIO_07: U58.12(B8) ; also on sheet 26
EXP_GPIO_08: U57.20(B1) ; also on sheet 26
EXP_GPIO_09: U57.18(B2) ; also on sheet 26
EXP_GPIO_10: U57.17(B3) ; also on sheet 26
EXP_GPIO_11: U57.16(B4) ; also on sheet 26
EXP_GPIO_12: U57.15(B5) ; also on sheet 26
EXP_GPIO_13: U57.14(B6) ; also on sheet 26
EXP_GPIO_14: U57.13(B7) ; also on sheet 26
EXP_GPIO_15: U57.12(B8) ; also on sheet 26
EXP_GPIO_16: U63.8(B1) ; also on sheet 26
EXP_GPIO_EN: R112.2 U57.10(OE) U58.10(OE) U63.6(OE) ; also on sheet 27
SOC_DDR3A_A0: U21.N3(A0) U26.N3(A0) U36.N3(A0) ; also on sheet 1 19
SOC_DDR3A_A1: U21.P7(A1) U26.P7(A1) U36.P7(A1) ; also on sheet 1 19
SOC_DDR3A_A2: U21.P3(A2) U26.P3(A2) U36.P3(A2) ; also on sheet 1 19
SOC_DDR3A_A3: U21.N2(A3) U26.N2(A3) U36.N2(A3) ; also on sheet 1 19
SOC_DDR3A_A4: U21.P8(A4) U26.P8(A4) U36.P8(A4) ; also on sheet 1 19
SOC_DDR3A_A5: U21.P2(A5) U26.P2(A5) U36.P2(A5) ; also on sheet 1 19
SOC_DDR3A_A6: U21.R8(A6) U26.R8(A6) U36.R8(A6) ; also on sheet 1 19
SOC_DDR3A_A7: U21.R2(A7) U26.R2(A7) U36.R2(A7) ; also on sheet 1 19
SOC_DDR3A_A8: U21.T8(A8) U26.T8(A8) U36.T8(A8) ; also on sheet 1 19
SOC_DDR3A_A9: U21.R3(A9) U26.R3(A9) U36.R3(A9) ; also on sheet 1 19
SOC_DDR3A_A10: U21.L7(A10/AP) U26.L7(A10/AP) U36.L7(A10/AP) ; also on sheet 1 19
SOC_DDR3A_A11: U21.R7(A11) U26.R7(A11) U36.R7(A11) ; also on sheet 1 19
SOC_DDR3A_A12: U21.N7(A12/BC#) U26.N7(A12/BC#) U36.N7(A12/BC#) ; also on sheet 1 19
SOC_DDR3A_A13: U21.T3(A13) U26.T3(A13) U36.T3(A13) ; also on sheet 1 19
SOC_DDR3A_A14: U21.T7(A14) U26.T7(A14) U36.T7(A14) ; also on sheet 1 19
SOC_DDR3A_A15: U21.M7(NC.3) U26.M7(NC.3) U36.M7(NC.3) ; also on sheet 1 19
SOC_DDR3A_BA_0: U21.M2(BA0) U26.M2(BA0) U36.M2(BA0) ; also on sheet 1 19
SOC_DDR3A_BA_1: U21.N8(BA1) U26.N8(BA1) U36.N8(BA1) ; also on sheet 1 19
SOC_DDR3A_BA_2: U21.M3(BA2) U26.M3(BA2) U36.M3(BA2) ; also on sheet 1 19
SOC_DDR3A_CAS#: U21.K3(CAS#) U26.K3(CAS#) U36.K3(CAS#) ; also on sheet 1 19
SOC_DDR3A_CKE_0: U21.K9(CKE) U26.K9(CKE) U36.K9(CKE) ; also on sheet 1 19
SOC_DDR3A_CKE_1: U21.J9(NC.4) U26.J9(NC.4) U36.J9(NC.4) ; also on sheet 1 19
SOC_DDR3A_CKN_0: U21.K7(CK#) U26.K7(CK#) U36.K7(CK#) ; also on sheet 1 19
SOC_DDR3A_CKP_0: U21.J7(CK) U26.J7(CK) U36.J7(CK) ; also on sheet 1 19
SOC_DDR3A_CS_0#: U21.L2(CS#) U26.L2(CS#) U36.L2(CS#) ; also on sheet 1 19
SOC_DDR3A_CS_1#: U21.L1(NC.2) U26.L1(NC.2) U36.L1(NC.2) ; also on sheet 1 19
SOC_DDR3A_DM_0: U21.E7(LDM) ; also on sheet 1
SOC_DDR3A_DM_1: U21.D3(UDM) ; also on sheet 1
SOC_DDR3A_DM_2: U26.E7(LDM) ; also on sheet 1
SOC_DDR3A_DM_3: U26.D3(UDM) ; also on sheet 1
SOC_DDR3A_DM_4: U36.E7(LDM) ; also on sheet 1
SOC_DDR3A_DM_5: U36.D3(UDM) ; also on sheet 1
SOC_DDR3A_DQ0: U21.H7(DQ7) ; also on sheet 1
SOC_DDR3A_DQ1: U21.G2(DQ6) ; also on sheet 1
SOC_DDR3A_DQ2: U21.H3(DQ4) ; also on sheet 1
SOC_DDR3A_DQ3: U21.E3(DQ0) ; also on sheet 1
SOC_DDR3A_DQ4: U21.F7(DQ1) ; also on sheet 1
SOC_DDR3A_DQ5: U21.F2(DQ2) ; also on sheet 1
SOC_DDR3A_DQ6: U21.F8(DQ3) ; also on sheet 1
SOC_DDR3A_DQ7: U21.H8(DQ5) ; also on sheet 1
SOC_DDR3A_DQ8: U21.A3(DQ15) ; also on sheet 1
SOC_DDR3A_DQ9: U21.A2(DQ13) ; also on sheet 1
SOC_DDR3A_DQ10: U21.C8(DQ10) ; also on sheet 1
SOC_DDR3A_DQ11: U21.A7(DQ12) ; also on sheet 1
SOC_DDR3A_DQ12: U21.C2(DQ11) ; also on sheet 1
SOC_DDR3A_DQ13: U21.B8(DQ14) ; also on sheet 1
SOC_DDR3A_DQ14: U21.C3(DQ9) ; also on sheet 1
SOC_DDR3A_DQ15: U21.D7(DQ8) ; also on sheet 1
SOC_DDR3A_DQ16: U26.H3(DQ4) ; also on sheet 1
SOC_DDR3A_DQ17: U26.F7(DQ1) ; also on sheet 1
SOC_DDR3A_DQ18: U26.H7(DQ7) ; also on sheet 1
SOC_DDR3A_DQ19: U26.F8(DQ3) ; also on sheet 1
SOC_DDR3A_DQ20: U26.E3(DQ0) ; also on sheet 1
SOC_DDR3A_DQ21: U26.H8(DQ5) ; also on sheet 1
SOC_DDR3A_DQ22: U26.G2(DQ6) ; also on sheet 1
SOC_DDR3A_DQ23: U26.F2(DQ2) ; also on sheet 1
SOC_DDR3A_DQ24: U26.C2(DQ11) ; also on sheet 1
SOC_DDR3A_DQ25: U26.C3(DQ9) ; also on sheet 1
SOC_DDR3A_DQ26: U26.A2(DQ13) ; also on sheet 1
SOC_DDR3A_DQ27: U26.A3(DQ15) ; also on sheet 1
SOC_DDR3A_DQ28: U26.A7(DQ12) ; also on sheet 1
SOC_DDR3A_DQ29: U26.B8(DQ14) ; also on sheet 1
SOC_DDR3A_DQ30: U26.C8(DQ10) ; also on sheet 1
SOC_DDR3A_DQ31: U26.D7(DQ8) ; also on sheet 1
SOC_DDR3A_DQ32: U36.H3(DQ4) ; also on sheet 1
SOC_DDR3A_DQ33: U36.F7(DQ1) ; also on sheet 1
SOC_DDR3A_DQ34: U36.F8(DQ3) ; also on sheet 1
SOC_DDR3A_DQ35: U36.H7(DQ7) ; also on sheet 1
SOC_DDR3A_DQ36: U36.E3(DQ0) ; also on sheet 1
SOC_DDR3A_DQ37: U36.H8(DQ5) ; also on sheet 1
SOC_DDR3A_DQ38: U36.F2(DQ2) ; also on sheet 1
SOC_DDR3A_DQ39: U36.G2(DQ6) ; also on sheet 1
SOC_DDR3A_DQ40: U36.A7(DQ12) ; also on sheet 1
SOC_DDR3A_DQ41: U36.A3(DQ15) ; also on sheet 1
SOC_DDR3A_DQ42: U36.C8(DQ10) ; also on sheet 1
SOC_DDR3A_DQ43: U36.A2(DQ13) ; also on sheet 1
SOC_DDR3A_DQ44: U36.C3(DQ9) ; also on sheet 1
SOC_DDR3A_DQ45: U36.D7(DQ8) ; also on sheet 1
SOC_DDR3A_DQ46: U36.C2(DQ11) ; also on sheet 1
SOC_DDR3A_DQ47: U36.B8(DQ14) ; also on sheet 1
SOC_DDR3A_DQSN_0: U21.G3(LDQS#) ; also on sheet 1
SOC_DDR3A_DQSN_1: U21.B7(UDQS#) ; also on sheet 1
SOC_DDR3A_DQSN_2: U26.G3(LDQS#) ; also on sheet 1
SOC_DDR3A_DQSN_3: U26.B7(UDQS#) ; also on sheet 1
SOC_DDR3A_DQSN_4: U36.G3(LDQS#) ; also on sheet 1
SOC_DDR3A_DQSN_5: U36.B7(UDQS#) ; also on sheet 1
SOC_DDR3A_DQSP_0: U21.F3(LDQS) ; also on sheet 1
SOC_DDR3A_DQSP_1: U21.C7(UDQS) ; also on sheet 1
SOC_DDR3A_DQSP_2: U26.F3(LDQS) ; also on sheet 1
SOC_DDR3A_DQSP_3: U26.C7(UDQS) ; also on sheet 1
SOC_DDR3A_DQSP_4: U36.F3(LDQS) ; also on sheet 1
SOC_DDR3A_DQSP_5: U36.C7(UDQS) ; also on sheet 1
SOC_DDR3A_ODT_0: U21.K1(ODT) U26.K1(ODT) U36.K1(ODT) ; also on sheet 1 19
SOC_DDR3A_ODT_1: U21.J1(NC.1) U26.J1(NC.1) U36.J1(NC.1) ; also on sheet 1 19
SOC_DDR3A_RAS#: U21.J3(RAS#) U26.J3(RAS#) U36.J3(RAS#) ; also on sheet 1 19
SOC_DDR3A_RESETN: U21.T2(RESET#) U26.T2(RESET#) U36.T2(RESET#) ; also on sheet 1 19
SOC_DDR3A_WE#: U21.L3(WE#) U26.L3(WE#) U36.L3(WE#) ; also on sheet 1 19
SOC_EMIFA00: U65.18(1Y1) ; also on sheet 26
SOC_EMIFA01: U65.16(1Y2) ; also on sheet 26
SOC_EMIFA02: U65.14(1Y3) ; also on sheet 26
SOC_EMIFA03: U65.12(1Y4) ; also on sheet 26
SOC_EMIFA04: U65.9(2Y1) ; also on sheet 26
SOC_EMIFA05: U65.7(2Y2) ; also on sheet 26
SOC_EMIFA06: U65.5(2Y3) ; also on sheet 26
SOC_EMIFA07: U65.3(2Y4) ; also on sheet 26
SOC_EMIFA08: U29.18(1Y1) ; also on sheet 26
SOC_EMIFA09: U29.16(1Y2) ; also on sheet 26
SOC_EMIFA10: U29.14(1Y3) ; also on sheet 26
SOC_EMIFA11: U29.12(1Y4) ; also on sheet 26
SOC_EMIFA12: U29.9(2Y1) ; also on sheet 26
SOC_EMIFA13: U29.7(2Y2) ; also on sheet 26
SOC_EMIFA14: U29.5(2Y3) ; also on sheet 26
SOC_EMIFA15: U29.3(2Y4) ; also on sheet 26
SOC_EMIFA16: U13.18(1Y1) ; also on sheet 26
SOC_EMIFA17: U13.16(1Y2) ; also on sheet 26
SOC_EMIFA18: U13.14(1Y3) ; also on sheet 26
SOC_EMIFA19: U13.12(1Y4) ; also on sheet 26
SOC_EMIFA20: U13.9(2Y1) ; also on sheet 26
SOC_EMIFA21: U13.7(2Y2) ; also on sheet 26
SOC_EMIFA22: U13.5(2Y3) ; also on sheet 26
SOC_EMIFA23: U13.3(2Y4) ; also on sheet 26
SOC_EMIFBE0Z: U60.18(1Y1) ; also on sheet 26
SOC_EMIFBE1Z: U60.16(1Y2) ; also on sheet 26
SOC_EMIFCE1Z: R581.2 U60.14(1Y3) ; also on sheet 26
SOC_EMIFCE2Z: R577.2 U60.12(1Y4) ; also on sheet 26
SOC_EMIFCE3Z: R575.2 U60.9(2Y1) ; also on sheet 26
SOC_EMIFD0: U62.18(B1) ; also on sheet 26
SOC_EMIFD1: U62.17(B2) ; also on sheet 26
SOC_EMIFD2: U62.16(B3) ; also on sheet 26
SOC_EMIFD3: U62.15(B4) ; also on sheet 26
SOC_EMIFD4: U62.14(B5) ; also on sheet 26
SOC_EMIFD5: U62.13(B6) ; also on sheet 26
SOC_EMIFD6: U62.12(B7) ; also on sheet 26
SOC_EMIFD7: U62.11(B8) ; also on sheet 26
SOC_EMIFD8: U22.18(B1) ; also on sheet 26
SOC_EMIFD9: U22.17(B2) ; also on sheet 26
SOC_EMIFD10: U22.16(B3) ; also on sheet 26
SOC_EMIFD11: U22.15(B4) ; also on sheet 26
SOC_EMIFD12: U22.14(B5) ; also on sheet 26
SOC_EMIFD13: U22.13(B6) ; also on sheet 26
SOC_EMIFD14: U22.12(B7) ; also on sheet 26
SOC_EMIFD15: U22.11(B8) ; also on sheet 26
SOC_EMIFOEZ: U60.5(2Y3) ; also on sheet 26
SOC_EMIFRNW: U60.7(2Y2) ; also on sheet 26
SOC_EMIFRNW_R: R608.1 U22.1(DIR) U62.1(DIR)
SOC_EMIFWEZ: U60.3(2Y4) ; also on sheet 26
SOC_GPIO_0_FPGA_1V8_EXP2: U58.1(A1) ; also on sheet 16 28
SOC_GPIO_1_FPGA_1V8_EXP2: U58.3(A2) ; also on sheet 16 28
SOC_GPIO_2_FPGA_1V8_EXP2: U58.4(A3) ; also on sheet 16 28
SOC_GPIO_3_FPGA_1V8_EXP2: U58.5(A4) ; also on sheet 16 28
SOC_GPIO_4_FPGA_1V8_EXP2: U58.6(A5) ; also on sheet 16 28
SOC_GPIO_5_FPGA_1V8_EXP2: U58.7(A6) ; also on sheet 16 28
SOC_GPIO_6_FPGA_1V8_EXP2: U58.8(A7) ; also on sheet 16 28
SOC_GPIO_7_FPGA_1V8_EXP2: U58.9(A8) ; also on sheet 6 16 28
SOC_GPIO_8_FPGA_1V8_EXP2: U57.1(A1) ; also on sheet 16 22 28
SOC_GPIO_9_FPGA_1V8_EXP2: U57.3(A2) ; also on sheet 16 28
SOC_GPIO_10_FPGA_1V8_EXP2: U57.4(A3) ; also on sheet 16 28
SOC_GPIO_11_FPGA_1V8_EXP2: U57.5(A4) ; also on sheet 16 22 28
SOC_GPIO_12_FPGA_1V8_EXP2: U57.6(A5) ; also on sheet 16 28
SOC_GPIO_13_FPGA_1V8_EXP2: U57.7(A6) ; also on sheet 16 28
SOC_GPIO_14_FPGA_1V8_EXP2: U57.8(A7) ; also on sheet 16 28
SOC_GPIO_15_FPGA_1V8_EXP2: U57.9(A8) ; also on sheet 16 28
SOC_GPIO_16_FPGA_1V8_EXP3: U63.5(A1) ; also on sheet 16 28
N17691414: R601.2 U21.L8(ZQ)
N17692357: R661.2 U36.L8(ZQ)
N17694704: R617.2 U26.L8(ZQ)
N19903320: R588.2 U21.L9(NC.5)
N19904582: R659.2 U36.L9(NC.5)
N19905831: R612.2 U26.L9(NC.5)

Not connected (* = marked no-connect by the designer): U63 1(B2)* 4(A2)*

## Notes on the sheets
sheet 20
- DDR3(3)
- Trace need 20 mil.
- Trace need 20 mil.
- * DDR3 pin M7 is used for
  A15 as per JEDC standard
- * DDR3 pin M7 is used for
  A15 as per JEDC standard
- * Data bits can be swapped within
  the byte lane to ease routing.
  * Address/Command/Control/Clock
  routing must be Fly-By in byte order
  0, 1, 2, 3 ECC, 4, 5, 6, 7.
- Trace need 20 mil.
- * DDR3 pin M7 is used for
  A15 as per JEDC standard
sheet 21
- EMIF Addr/Cntl Buffer, Ext EMIF_OE, EMIF Data Transceiver
- EMIF Addr/Cntl Buffer
- External EMIFA Access
  CE1, CE2, or CE3
